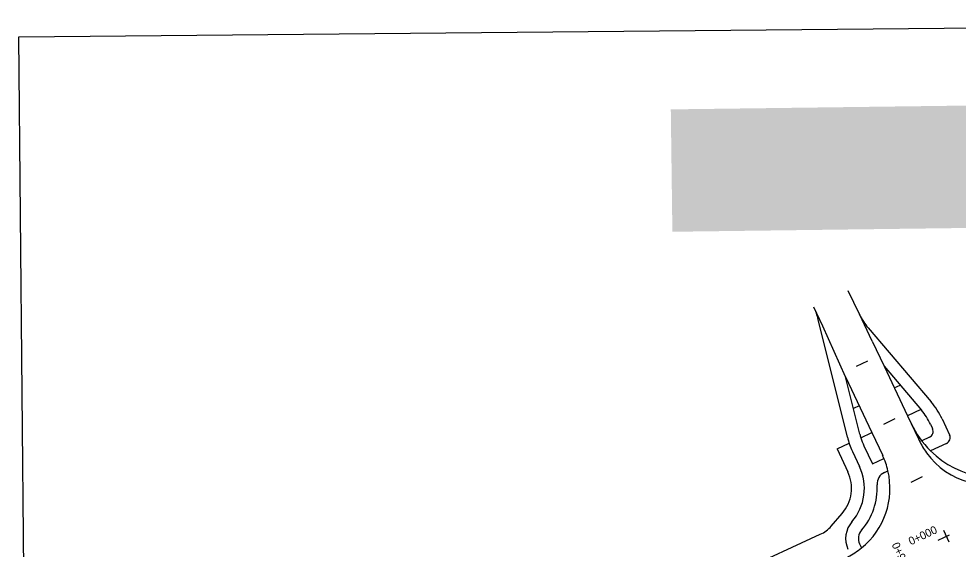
# Model space of a CAD drawing. Extents: x 6503541 to 6503743, y 5888004 to 5888145.
# Drawn here: x 6503614.098 to 6503617.619, y 5888061.805 to 5888063.792 of the extents above; entities that cross this region are included whole.
import ezdxf

# ---------------------------------------------------------------- set-up
doc = ezdxf.new("R2010")
doc.units = 0
doc.layers.add('12', color=7, linetype='Continuous')
doc.layers.add('tabela', color=7, linetype='Continuous')

msp = doc.modelspace()

# ---------------------------------------------------------------- linework, layer by layer
at = {"layer": '12'}
for p, q in [((6503617.2483, 5888062.6852), (6503617.2062, 5888062.773)), ((6503617.1119, 5888062.6407), (6503617.0776, 5888062.7118)), ((6503617.2033, 5888062.2246), (6503617.0944, 5888062.6652)), ((6503617.2962, 5888062.5844), (6503617.2483, 5888062.6852)), ((6503617.1968, 5888062.451), (6503617.1119, 5888062.6407)), ((6503617.2818, 5888062.6337), (6503617.5174, 5888062.3564)), ((6503617.2962, 5888062.5844), (6503617.341, 5888062.4899)), ((6503617.341, 5888062.4899), (6503617.4809, 5888062.3253)), ((6503617.341, 5888062.4899), (6503617.4286, 5888062.3049)), ((6503617.1968, 5888062.451), (6503617.2951, 5888062.2417)), ((6503617.2499, 5888062.2361), (6503617.1968, 5888062.451)), ((6503617.3793, 5888062.4089), (6503617.401, 5888062.4192)), ((6503617.2479, 5888062.3422), (6503617.2262, 5888062.332)), ((6503617.4782, 5888062.3284), (6503617.4286, 5888062.3049)), ((6503617.4286, 5888062.3049), (6503617.4697, 5888062.2181)), ((6503617.5582, 5888062.2932), (6503617.5866, 5888062.2333)), ((6503617.2538, 5888062.2221), (6503617.2951, 5888062.2417)), ((6503617.2951, 5888062.2417), (6503617.3357, 5888062.1554)), ((6503617.5148, 5888062.2727), (6503617.5226, 5888062.2563)), ((6503617.4697, 5888062.2181), (6503617.4728, 5888062.2115)), ((6503617.5111, 5888062.2243), (6503617.4821, 5888062.2107)), ((6503617.1648, 5888062.1804), (6503617.21, 5888062.2016)), ((6503617.1648, 5888062.1805), (6503617.2054, 5888062.0942)), ((6503617.2222, 5888062.1712), (6503617.2488, 5888062.1146)), ((6503617.2657, 5888062.1916), (6503617.2973, 5888062.1242)), ((6503617.5751, 5888062.2013), (6503617.5153, 5888062.1732)), ((6503617.2973, 5888062.1242), (6503617.3406, 5888062.1444)), ((6503617.3423, 5888062.0922), (6503617.3555, 5888062.0984)), ((6503617.1428, 5888061.8911), (6503617.184, 5888061.9388)), ((6503616.1313, 5888061.4154), (6503617.102, 5888061.8605)), ((6503617.2494, 5888061.8246), (6503617.2564, 5888061.8092))]:
    msp.add_line(p, q, dxfattribs=at)
for points in [[(6503617.2793, 5888062.5096), (6503617.2359, 5888062.4891)], [(6503617.3818, 5888062.2926), (6503617.3383, 5888062.2721)], [(6503617.4842, 5888062.0756), (6503617.4408, 5888062.0551)], [(6503617.5433, 5888061.8381), (6503617.5867, 5888061.8586)], [(6503617.5845, 5888061.8309), (6503617.5645, 5888061.8745)]]:
    msp.add_lwpolyline(points, dxfattribs=at)
for centre, radius, start, end in [((6503616.8614, 5888062.6076), 0.24, 13.878, 25.7291), ((6503617.4647, 5888062.7891), 0.24, 205.6508, 220.3545), ((6503617.298, 5888062.1699), 0.288, 25.3545, 40.3545), ((6503617.298, 5888062.1699), 0.24, 25.3545, 40.3545), ((6503617.7678, 5888062.4298), 0.36, 205.3174, 225.444), ((6503617.5009, 5888062.246), 0.024, 295.0908, 25.3545), ((6503617.4829, 5888062.2937), 0.288, 193.878, 205.1718), ((6503617.4829, 5888062.2937), 0.24, 193.878, 197.3529), ((6503617.4829, 5888062.2937), 0.24, 197.3529, 205.1718), ((6503617.7332, 5888062.3347), 0.288, 205.3174, 215.8539), ((6503617.5649, 5888062.223), 0.024, 295.0908, 25.3545), ((6503617.7678, 5888062.4298), 0.36, 225.444, 294.6311), ((6503617.075, 5888062.0329), 0.288, 13.1489, 25.1718), ((6503617.7332, 5888062.3347), 0.288, 215.8539, 294.6311), ((6503617.075, 5888062.0329), 0.192, 319.1796, 25.1718), ((6503617.075, 5888062.0329), 0.144, 319.1796, 25.1718), ((6503617.075, 5888062.0329), 0.288, 309.0375, 13.1489), ((6503617.3626, 5888062.0487), 0.048, 115.0908, 183.1538), ((6503617.075, 5888062.0329), 0.24, 319.1796, 3.1538), ((6503617.052, 5888061.9695), 0.12, 294.6311, 319.1796), ((6503617.293, 5888061.8446), 0.096, 139.1796, 204.6311), ((6503617.293, 5888061.8446), 0.048, 139.1796, 204.6311), ((6503617.075, 5888062.0329), 0.288, 296.9501, 309.0375)]:
    msp.add_arc(centre, radius, start, end, dxfattribs=at)
at = {"layer": 'tabela'}
for p, q in [((6503614.0979, 5888063.7245), (6503621.3333, 5888063.7921)), ((6503614.0979, 5888063.7245), (6503621.3333, 5888063.7921)), ((6503614.1447, 5888058.7044), (6503614.0979, 5888063.7245)), ((6503614.1447, 5888058.7044), (6503614.0979, 5888063.7245))]:
    msp.add_line(p, q, dxfattribs=at)

# ---------------------------------------------------------------- texts
at = {"layer": '12'}
for s, height, rotation, p in [('7', 4.223, 0.7393, (6503616.3066, 5888059.2262)), ('0+000', 0.03, 25.2768, (6503617.4414, 5888061.8188)), ('0+900', 0.03, 294.6311, (6503617.3686, 5888061.8219))]:
    msp.add_text(s, height=height, rotation=rotation, dxfattribs=at).set_placement(p)

doc.saveas('drawing.dxf')
